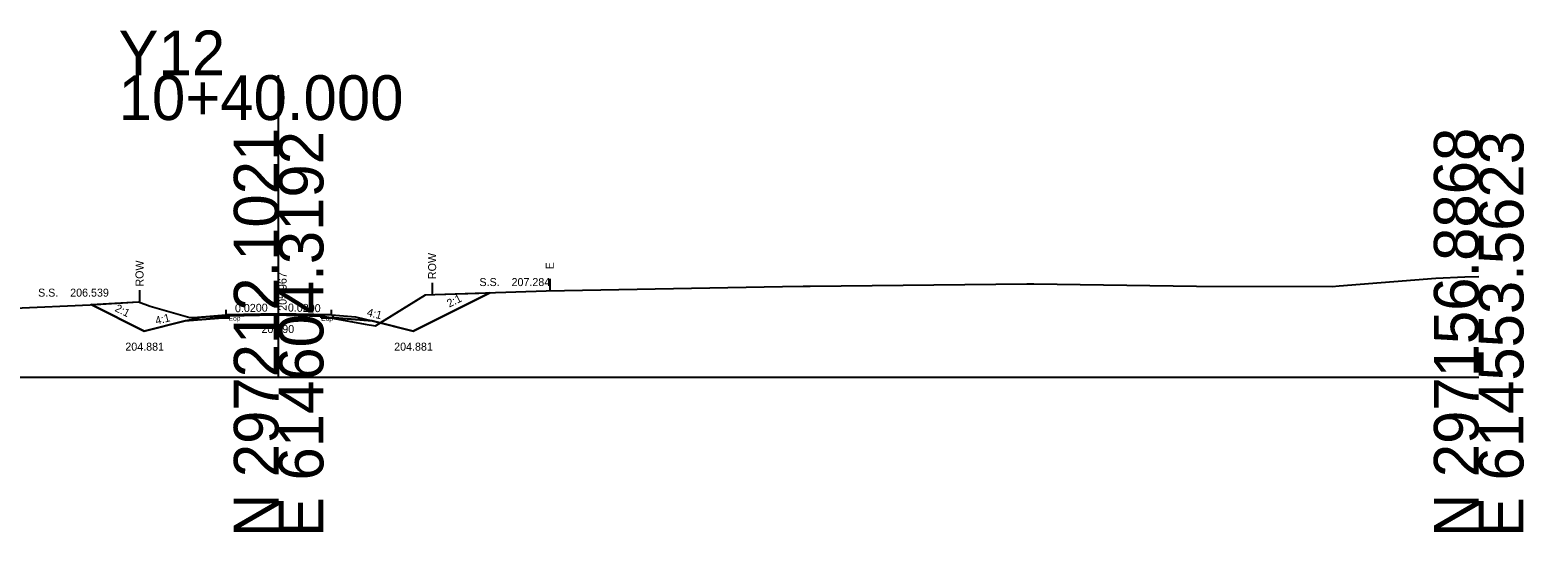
# Model space of a CAD drawing. Extents: x 517327 to 517505, y 114839 to 117367.
# Drawn here: x 517411.8 to 517505.2, y 115838.7 to 115870.1 of the extents above; entities that cross this region are included whole.
import ezdxf

# ---------------------------------------------------------------- set-up
doc = ezdxf.new("R2010")
doc.units = 0
for name, color, linetype in [('Exist XS Ground Line', 7, 'Continuous'), ('Old_Level_3', 7, 'Continuous'), ('Old_Level_5', 7, 'Continuous'), ('Old_Level_59', 7, 'Continuous'), ('Old_Level_63', 7, 'Continuous'), ('Prop XS Dump Level', 7, 'Continuous'), ('Prop XS Earthwork Shape', 7, 'Continuous'), ('Prop XS Elevation Labels', 7, 'Continuous'), ('Prop XS EOT Tick Mark', 7, 'Continuous'), ('Prop XS Exc Vertical Line 1', 7, 'Continuous'), ('Prop XS Exc Vertical Line 2', 7, 'Continuous'), ('Prop XS Finish Grade', 7, 'Continuous'), ('Prop XS Finish Grade Earthwork', 7, 'Continuous'), ('Prop XS Finish Grade Pavement', 7, 'Continuous'), ('Prop XS Hydro Elevations', 7, 'Continuous'), ('Prop XS Pvmt Edge Slope', 7, 'Continuous'), ('Prop XS Side Slope Text', 7, 'Continuous'), ('Prop XS Subgrade Earthwork', 7, 'Continuous'), ('Prop XS Suitable Common Exc Shape', 7, 'Continuous')]:
    doc.layers.add(name, color=color, linetype=linetype)

msp = doc.modelspace()

# ---------------------------------------------------------------- linework, layer by layer
at = {"layer": 'Exist XS Ground Line'}
for p, q in [((517437.133, 115853.534), (517444.095, 115853.767)), ((517444.095, 115853.767), (517458.853, 115854.046)), ((517458.853, 115854.046), (517460.141, 115854.063)), ((517460.141, 115854.063), (517460.576, 115854.06)), ((517460.576, 115854.06), (517474.128, 115854.21)), ((517474.128, 115854.21), (517474.558, 115854.203)), ((517474.558, 115854.203), (517483.268, 115854.085)), ((517483.268, 115854.085), (517484.735, 115854.061)), ((517484.735, 115854.061), (517493.215, 115854.033)), ((517493.215, 115854.033), (517493.651, 115854.079)), ((517493.651, 115854.079), (517499.687, 115854.566)), ((517499.687, 115854.566), (517501.496, 115854.639)), ((517501.496, 115854.639), (517502.365, 115854.662)), ((517410.865, 115852.681), (517415.592, 115852.901)), ((517415.592, 115852.901), (517418.616, 115853.08)), ((517418.616, 115853.08), (517419.344, 115852.816)), ((517419.344, 115852.816), (517421.823, 115852.097)), ((517433.425, 115851.576), (517436.55, 115853.514)), ((517436.55, 115853.514), (517437.133, 115853.534)), ((517421.823, 115852.097), (517424.246, 115852.199)), ((517424.246, 115852.199), (517427.138, 115852.269)), ((517427.138, 115852.269), (517430.029, 115852.186)), ((517430.029, 115852.186), (517432.767, 115851.69)), ((517432.767, 115851.69), (517433.425, 115851.576))]:
    msp.add_line(p, q, dxfattribs=at)
at = {"layer": 'Old_Level_63'}
for p, q in [((517427.365, 115848.365), (517427.365, 115867.255)), ((517352.365, 115848.365), (517427.365, 115848.365)), ((517427.365, 115848.365), (517502.365, 115848.365))]:
    msp.add_line(p, q, dxfattribs=at)
at = {"layer": 'Prop XS Dump Level'}
for p, q in [((517424.065, 115852.266), (517427.365, 115852.332)), ((517427.365, 115852.332), (517430.665, 115852.266))]:
    msp.add_line(p, q, dxfattribs=at)
at = {"layer": 'Prop XS Earthwork Shape'}
for points in [[(517415.647, 115852.904), (517418.616, 115853.08), (517419.344, 115852.816), (517421.823, 115852.097), (517424.246, 115852.199), (517424.244, 115852.079), (517424.065, 115852.076), (517423.871, 115852.072), (517422.565, 115851.967), (517421.516, 115851.883), (517418.965, 115851.246)], [(517433.718, 115851.757), (517436.55, 115853.514), (517437.133, 115853.534), (517440.572, 115853.649), (517435.765, 115851.246)], [(517430.029, 115852.088), (517430.027, 115852.186), (517430.632, 115852.076)], [(517430.632, 115852.076), (517432.767, 115851.69), (517433.425, 115851.576), (517433.718, 115851.757), (517433.214, 115851.883), (517432.165, 115851.967), (517430.859, 115852.072), (517430.665, 115852.076)]]:
    msp.add_lwpolyline(points, close=True, dxfattribs=at)
at = {"layer": 'Prop XS EOT Tick Mark'}
for p, q in [((517424.065, 115852.57), (517424.065, 115852.266)), ((517430.665, 115852.266), (517430.665, 115852.57))]:
    msp.add_line(p, q, dxfattribs=at)
at = {"layer": 'Prop XS Exc Vertical Line 1'}
msp.add_line((517444.312, 115854.521), (517444.312, 115853.771), dxfattribs=at)
at = {"layer": 'Prop XS Exc Vertical Line 2'}
for p, q in [((517418.671, 115853.81), (517418.671, 115853.06)), ((517436.959, 115854.278), (517436.959, 115853.528))]:
    msp.add_line(p, q, dxfattribs=at)
at = {"layer": 'Prop XS Finish Grade'}
for p, q in [((517421.516, 115851.883), (517422.565, 115852.145)), ((517422.565, 115852.145), (517424.065, 115852.266)), ((517430.665, 115852.266), (517432.165, 115852.145)), ((517432.165, 115852.145), (517433.214, 115851.883))]:
    msp.add_line(p, q, dxfattribs=at)
at = {"layer": 'Prop XS Finish Grade Earthwork'}
for p, q in [((517415.647, 115852.904), (517418.965, 115851.246)), ((517435.765, 115851.246), (517440.572, 115853.649)), ((517418.965, 115851.246), (517421.516, 115851.883)), ((517433.214, 115851.883), (517435.765, 115851.246))]:
    msp.add_line(p, q, dxfattribs=at)
at = {"layer": 'Prop XS Finish Grade Pavement'}
for p, q in [((517427.365, 115852.332), (517424.065, 115852.266)), ((517430.665, 115852.266), (517427.365, 115852.332))]:
    msp.add_line(p, q, dxfattribs=at)
at = {"layer": 'Prop XS Pvmt Edge Slope'}
for p, q in [((517423.871, 115852.072), (517424.065, 115852.266)), ((517430.665, 115852.266), (517430.859, 115852.072))]:
    msp.add_line(p, q, dxfattribs=at)
at = {"layer": 'Prop XS Subgrade Earthwork'}
for p, q in [((517421.516, 115851.883), (517422.565, 115851.967)), ((517422.565, 115851.967), (517423.871, 115852.072)), ((517423.871, 115852.072), (517424.065, 115852.076)), ((517424.065, 115852.076), (517424.244, 115852.079)), ((517424.246, 115852.199), (517424.244, 115852.079)), ((517430.029, 115852.088), (517430.027, 115852.186)), ((517430.029, 115852.088), (517430.665, 115852.076)), ((517430.665, 115852.076), (517430.859, 115852.072)), ((517430.859, 115852.072), (517432.165, 115851.967)), ((517432.165, 115851.967), (517433.214, 115851.883))]:
    msp.add_line(p, q, dxfattribs=at)
at = {"layer": 'Prop XS Suitable Common Exc Shape'}
for points in [[(517421.823, 115852.097), (517424.246, 115852.199), (517424.244, 115852.079), (517424.065, 115852.076), (517423.871, 115852.072), (517422.565, 115851.967), (517421.516, 115851.883), (517418.965, 115851.246), (517415.647, 115852.904), (517418.616, 115853.08), (517419.344, 115852.816)], [(517437.133, 115853.534), (517440.572, 115853.649), (517435.765, 115851.246), (517433.718, 115851.757), (517436.55, 115853.514)], [(517430.029, 115852.088), (517430.634, 115852.076), (517430.029, 115852.186)], [(517433.425, 115851.576), (517433.718, 115851.757), (517433.214, 115851.883), (517432.165, 115851.967), (517430.859, 115852.072), (517430.665, 115852.076), (517430.634, 115852.076), (517432.767, 115851.69)]]:
    msp.add_lwpolyline(points, close=True, dxfattribs=at)

# ---------------------------------------------------------------- texts
at = {"layer": 'Old_Level_3'}
for rotation, p in [(14.03624, (517419.72, 115851.649)), (345.96376, (517432.85, 115852.209))]:
    msp.add_text('4:1', height=0.5, rotation=rotation, dxfattribs=at).set_placement(p)
at = {"layer": 'Old_Level_5'}
for rotation, p in [(1.14576, (517424.642, 115852.429)), (358.85423, (517427.942, 115852.472))]:
    msp.add_text('0.0200', height=0.5, rotation=rotation, dxfattribs=at).set_placement(p)
at = {"layer": 'Old_Level_59'}
msp.add_text(' 205.967', height=0.5, rotation=90, dxfattribs=at).set_placement((517427.865, 115852.332))
msp.add_text(' 205.967', height=0.5, rotation=90, dxfattribs=at).set_placement((517427.865, 115852.332))
msp.add_text(' 205.967', height=0.5, rotation=90, dxfattribs=at).set_placement((517427.865, 115852.332))
msp.add_text('205.90', height=0.5, dxfattribs=at).set_placement((517426.292, 115851.13))
at = {"layer": 'Old_Level_63'}
for s, p in [('Y12', (517417.362, 115867.255)), ('10+40.000', (517417.365, 115864.455))]:
    msp.add_text(s, height=2.8, dxfattribs=at).set_placement(p)
for s, p in [('N 297212.1021', (517427.365, 115838.365)), ('E 614604.3192', (517430.165, 115838.364)), ('N 297156.8868', (517502.365, 115838.365)), ('E 614553.5623', (517505.165, 115838.365))]:
    msp.add_text(s, height=2.8, rotation=90, dxfattribs=at).set_placement(p)
at = {"layer": 'Prop XS Elevation Labels'}
for s, height, p in [('Case1', 0.0122, (517422.565, 115852.133)), ('Eop', 0.3, (517424.244, 115851.899)), ('Eop', 0.3, (517430.029, 115851.886)), ('Case1', 0.0122, (517432.165, 115852.133))]:
    msp.add_text(s, height=height, dxfattribs=at).set_placement(p)
at = {"layer": 'Prop XS Exc Vertical Line 1'}
msp.add_text('E', height=0.5, rotation=90, dxfattribs=at).set_placement((517444.562, 115855.114))
at = {"layer": 'Prop XS Exc Vertical Line 2'}
for p in [(517418.921, 115854.035), (517437.209, 115854.503)]:
    msp.add_text('ROW', height=0.5, rotation=90, dxfattribs=at).set_placement(p)
at = {"layer": 'Prop XS Hydro Elevations'}
for s, p in [('S.S.    206.539', (517412.332, 115853.406)), ('S.S.    207.284', (517439.916, 115854.067))]:
    msp.add_text(s, height=0.5, dxfattribs=at).set_placement(p)
at = {"layer": 'Prop XS Side Slope Text'}
for rotation, p in [(333.43495, (517417.086, 115852.52)), (26.56505, (517438.034, 115852.716))]:
    msp.add_text('2:1', height=0.5, rotation=rotation, dxfattribs=at).set_placement(p)
for p in [(517417.786, 115850.026), (517434.586, 115850.026)]:
    msp.add_text('204.881', height=0.5, dxfattribs=at).set_placement(p)

doc.saveas('drawing.dxf')
